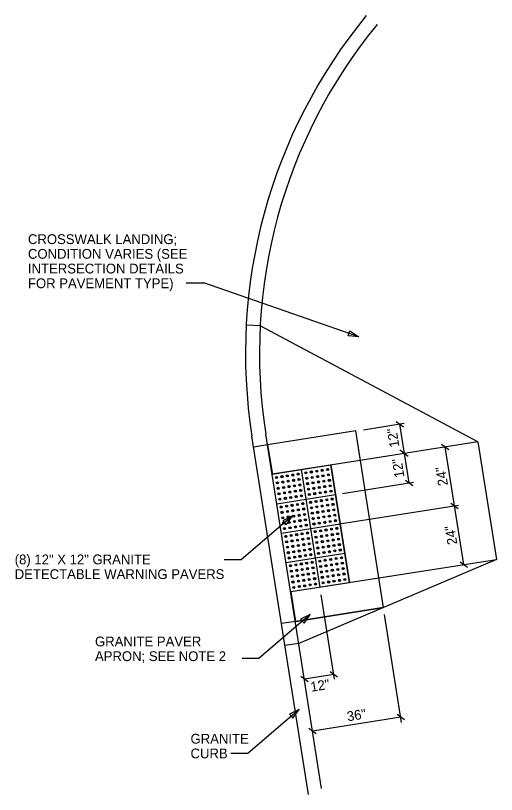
# Model space of a CAD drawing. Extents: x -848 to 1, y -1131 to -115.
# Drawn here: x -441.8 to -373.1, y -877.9 to -766.6 of the extents above; entities that cross this region are included whole.
import ezdxf

# ---------------------------------------------------------------- set-up
doc = ezdxf.new("R2010")
doc.units = 0
for name, color, linetype in [('PV_P_Curb', 7, 'Continuous'), ('PV_P_Curb_Ramp', 7, 'Continuous'), ('PV_P_Joint', 7, 'Continuous'), ('SC_Scratch3', 7, 'Continuous'), ('TX_X_5', 7, 'Continuous')]:
    doc.layers.add(name, color=color, linetype=linetype)

msp = doc.modelspace()

# ---------------------------------------------------------------- linework, layer by layer
at = {"layer": 'PV_P_Curb'}
for p, q in [((-398.03, -877.02), (-406.01, -826.38)), ((-389.2, -851.15), (-393.17, -825.94)), ((-399.92, -877.85), (-407.99, -826.69)), ((-394.06, -847.61), (-396.71, -830.8)), ((-398.26, -848.28), (-400.91, -831.46))]:
    msp.add_line(p, q, dxfattribs=at)
for radius in [76, 74]:
    msp.add_arc((-332.92, -814.85), radius, 140.6083, 188.9617, dxfattribs=at)
at = {"layer": 'PV_P_Curb_Ramp'}
for p, q in [((-406.81, -810.94), (-408.81, -810.83)), ((-375.71, -827.49), (-406.81, -810.94)), ((-393.17, -825.94), (-405.77, -827.93)), ((-375.71, -827.49), (-392.51, -830.14)), ((-375.71, -827.49), (-373.06, -844.29)), ((-405.77, -827.93), (-407.74, -828.24)), ((-392.51, -830.14), (-405.11, -832.12)), ((-404.44, -836.33), (-396.05, -835.01)), ((-403.78, -840.53), (-395.38, -839.21)), ((-403.12, -844.73), (-394.72, -843.41)), ((-373.06, -844.29), (-401.3, -856.29)), ((-389.86, -846.94), (-373.06, -844.29)), ((-389.86, -846.95), (-402.45, -848.94)), ((-389.2, -851.15), (-401.79, -853.14)), ((-401.79, -853.14), (-403.77, -853.45)), ((-401.3, -856.29), (-403.27, -856.6))]:
    msp.add_line(p, q, dxfattribs=at)
at = {"layer": 'PV_P_Joint'}
for p, q in [((-393.17, -825.94), (-405.77, -827.93)), ((-389.2, -851.15), (-393.17, -825.94)), ((-405.77, -827.93), (-405.77, -827.93)), ((-405.77, -827.93), (-405.07, -832.18)), ((-405.11, -832.12), (-396.71, -830.8)), ((-396.71, -830.8), (-394.06, -847.61)), ((-405.07, -832.18), (-405.11, -832.12)), ((-394.06, -847.61), (-402.45, -848.94))]:
    msp.add_line(p, q, dxfattribs=at)
msp.add_lwpolyline([(-402.45, -848.94), (-401.79, -853.14), (-389.2, -851.15)], dxfattribs=at)
at = {"layer": 'SC_Scratch3'}
for centre, radius in [((-401.38, -832.1), 0.15), ((-400.28, -831.93), 0.15), ((-400.28, -831.93), 0.0667), ((-400.28, -831.93), 0.0667), ((-399.5, -831.81), 0.15), ((-399.5, -831.81), 0.0667), ((-399.5, -831.81), 0.0667), ((-398.73, -831.69), 0.15), ((-398.73, -831.69), 0.0667), ((-398.73, -831.69), 0.0667), ((-397.96, -831.57), 0.15), ((-397.96, -831.57), 0.0667), ((-397.96, -831.57), 0.0667), ((-397.18, -831.45), 0.15), ((-397.18, -831.45), 0.0667), ((-397.18, -831.45), 0.0667), ((-404.48, -832.59), 0.15), ((-404.48, -832.59), 0.0667), ((-404.48, -832.59), 0.0667), ((-403.7, -832.47), 0.15), ((-403.7, -832.47), 0.0667), ((-403.7, -832.47), 0.0667), ((-403.58, -833.24), 0.15), ((-402.93, -832.35), 0.15), ((-402.93, -832.35), 0.0667), ((-402.93, -832.35), 0.0667), ((-402.81, -833.12), 0.15), ((-402.81, -833.12), 0.0667), ((-402.81, -833.12), 0.0667), ((-402.16, -832.23), 0.15), ((-402.16, -832.23), 0.0667), ((-402.16, -832.23), 0.0667), ((-402.04, -833), 0.15), ((-402.04, -833), 0.0667), ((-402.04, -833), 0.0667), ((-401.38, -832.1), 0.0667), ((-401.38, -832.1), 0.0667), ((-401.26, -832.88), 0.15), ((-401.26, -832.88), 0.0667), ((-401.26, -832.88), 0.0667), ((-400.16, -832.7), 0.15), ((-400.16, -832.7), 0.0667), ((-400.16, -832.7), 0.0667), ((-399.38, -832.58), 0.15), ((-399.38, -832.58), 0.0667), ((-399.38, -832.58), 0.0667), ((-398.61, -832.46), 0.15), ((-398.61, -832.46), 0.0667), ((-398.61, -832.46), 0.0667), ((-398.49, -833.23), 0.15), ((-397.84, -832.34), 0.15), ((-397.84, -832.34), 0.0667), ((-397.84, -832.34), 0.0667), ((-397.72, -833.11), 0.15), ((-397.72, -833.11), 0.0667), ((-397.72, -833.11), 0.0667), ((-397.06, -832.22), 0.15), ((-397.06, -832.22), 0.0667), ((-397.06, -832.22), 0.0667), ((-396.94, -832.99), 0.15), ((-396.94, -832.99), 0.0667), ((-396.94, -832.99), 0.0667), ((-404.36, -833.36), 0.15), ((-404.36, -833.36), 0.0667), ((-404.36, -833.36), 0.0667), ((-404.24, -834.13), 0.15), ((-404.24, -834.13), 0.0667), ((-404.24, -834.13), 0.0667), ((-403.58, -833.24), 0.0667), ((-403.58, -833.24), 0.0667), ((-403.46, -834.01), 0.15), ((-403.46, -834.01), 0.0667), ((-403.46, -834.01), 0.0667), ((-402.69, -833.89), 0.15), ((-402.69, -833.89), 0.0667), ((-402.69, -833.89), 0.0667), ((-401.91, -833.77), 0.15), ((-401.91, -833.77), 0.0667), ((-401.91, -833.77), 0.0667), ((-401.14, -833.65), 0.15), ((-401.14, -833.65), 0.0667), ((-401.14, -833.65), 0.0667), ((-400.04, -833.47), 0.15), ((-400.04, -833.47), 0.0667), ((-400.04, -833.47), 0.0667), ((-399.92, -834.25), 0.15), ((-399.92, -834.25), 0.0667), ((-399.92, -834.25), 0.0667), ((-399.26, -833.35), 0.15), ((-399.26, -833.35), 0.0667), ((-399.26, -833.35), 0.0667), ((-399.14, -834.13), 0.15), ((-399.14, -834.13), 0.0667), ((-399.14, -834.13), 0.0667), ((-398.49, -833.23), 0.0667), ((-398.49, -833.23), 0.0667), ((-398.37, -834.01), 0.15), ((-398.37, -834.01), 0.0667), ((-398.37, -834.01), 0.0667), ((-397.6, -833.89), 0.15), ((-397.6, -833.89), 0.0667), ((-397.6, -833.89), 0.0667), ((-396.82, -833.77), 0.15), ((-396.82, -833.77), 0.0667), ((-396.82, -833.77), 0.0667), ((-404.12, -834.91), 0.15), ((-404.12, -834.91), 0.0667), ((-404.12, -834.91), 0.0667), ((-403.34, -834.79), 0.15), ((-403.34, -834.79), 0.0667), ((-403.34, -834.79), 0.0667), ((-402.57, -834.67), 0.15), ((-402.57, -834.67), 0.0667), ((-402.57, -834.67), 0.0667), ((-402.45, -835.44), 0.15), ((-401.79, -834.55), 0.15), ((-401.79, -834.55), 0.0667), ((-401.79, -834.55), 0.0667), ((-401.67, -835.32), 0.15), ((-401.67, -835.32), 0.0667), ((-401.67, -835.32), 0.0667), ((-401.02, -834.43), 0.15), ((-401.02, -834.43), 0.0667), ((-401.02, -834.43), 0.0667), ((-400.9, -835.2), 0.15), ((-400.9, -835.2), 0.0667), ((-400.9, -835.2), 0.0667), ((-399.8, -835.02), 0.15), ((-399.8, -835.02), 0.0667), ((-399.8, -835.02), 0.0667), ((-399.02, -834.9), 0.15), ((-399.02, -834.9), 0.0667), ((-399.02, -834.9), 0.0667), ((-398.25, -834.78), 0.15), ((-398.25, -834.78), 0.0667), ((-398.25, -834.78), 0.0667), ((-397.47, -834.66), 0.15), ((-397.47, -834.66), 0.0667), ((-397.47, -834.66), 0.0667), ((-396.7, -834.54), 0.15), ((-396.7, -834.54), 0.0667), ((-396.7, -834.54), 0.0667), ((-404, -835.68), 0.15), ((-404, -835.68), 0.0667), ((-404, -835.68), 0.0667), ((-403.22, -835.56), 0.15), ((-403.22, -835.56), 0.0667), ((-403.22, -835.56), 0.0667), ((-402.45, -835.44), 0.0667), ((-402.45, -835.44), 0.0667), ((-402.26, -836.56), 0.15), ((-401.49, -836.44), 0.15), ((-401.49, -836.44), 0.0667), ((-401.49, -836.44), 0.0667), ((-400.72, -836.32), 0.15), ((-400.72, -836.32), 0.0667), ((-400.72, -836.32), 0.0667), ((-399.61, -836.14), 0.15), ((-399.61, -836.14), 0.0667), ((-399.61, -836.14), 0.0667), ((-398.84, -836.02), 0.15), ((-398.84, -836.02), 0.0667), ((-398.84, -836.02), 0.0667), ((-398.07, -835.9), 0.15), ((-398.07, -835.9), 0.0667), ((-398.07, -835.9), 0.0667), ((-397.29, -835.78), 0.15), ((-397.29, -835.78), 0.0667), ((-397.29, -835.78), 0.0667), ((-397.17, -836.55), 0.15), ((-397.17, -836.55), 0.0667), ((-397.17, -836.55), 0.0667), ((-396.52, -835.66), 0.15), ((-396.52, -835.66), 0.0667), ((-396.52, -835.66), 0.0667), ((-396.4, -836.43), 0.15), ((-396.4, -836.43), 0.0667), ((-396.4, -836.43), 0.0667), ((-403.81, -836.8), 0.15), ((-403.81, -836.8), 0.0667), ((-403.81, -836.8), 0.0667), ((-403.69, -837.57), 0.15), ((-403.69, -837.57), 0.0667), ((-403.69, -837.57), 0.0667), ((-403.04, -836.68), 0.15), ((-403.04, -836.68), 0.0667), ((-403.04, -836.68), 0.0667), ((-402.92, -837.45), 0.15), ((-402.92, -837.45), 0.0667), ((-402.92, -837.45), 0.0667), ((-402.26, -836.56), 0.0667), ((-402.26, -836.56), 0.0667), ((-402.14, -837.33), 0.15), ((-402.14, -837.33), 0.0667), ((-402.14, -837.33), 0.0667), ((-401.37, -837.21), 0.15), ((-401.37, -837.21), 0.0667), ((-401.37, -837.21), 0.0667), ((-400.6, -837.09), 0.15), ((-400.6, -837.09), 0.0667), ((-400.6, -837.09), 0.0667), ((-399.49, -836.91), 0.15), ((-399.49, -836.91), 0.0667), ((-399.49, -836.91), 0.0667), ((-399.37, -837.68), 0.15), ((-398.72, -836.79), 0.15), ((-398.72, -836.79), 0.0667), ((-398.72, -836.79), 0.0667), ((-398.6, -837.56), 0.15), ((-398.6, -837.56), 0.0667), ((-398.6, -837.56), 0.0667), ((-397.95, -836.67), 0.15), ((-397.95, -836.67), 0.0667), ((-397.95, -836.67), 0.0667), ((-397.83, -837.44), 0.15), ((-397.83, -837.44), 0.0667), ((-397.83, -837.44), 0.0667), ((-397.05, -837.32), 0.15), ((-397.05, -837.32), 0.0667), ((-397.05, -837.32), 0.0667), ((-396.28, -837.2), 0.15), ((-396.28, -837.2), 0.0667), ((-396.28, -837.2), 0.0667), ((-403.57, -838.35), 0.15), ((-403.57, -838.35), 0.0667), ((-403.57, -838.35), 0.0667), ((-402.8, -838.23), 0.15), ((-402.8, -838.23), 0.0667), ((-402.8, -838.23), 0.0667), ((-402.02, -838.11), 0.15), ((-402.02, -838.11), 0.0667), ((-402.02, -838.11), 0.0667), ((-401.25, -837.99), 0.15), ((-401.25, -837.99), 0.0667), ((-401.25, -837.99), 0.0667), ((-401.13, -838.76), 0.15), ((-401.13, -838.76), 0.0667), ((-401.13, -838.76), 0.0667), ((-400.48, -837.87), 0.15), ((-400.48, -837.87), 0.0667), ((-400.48, -837.87), 0.0667), ((-400.36, -838.64), 0.15), ((-400.36, -838.64), 0.0667), ((-400.36, -838.64), 0.0667), ((-399.37, -837.68), 0.0667), ((-399.37, -837.68), 0.0667), ((-399.25, -838.46), 0.15), ((-399.25, -838.46), 0.0667), ((-399.25, -838.46), 0.0667), ((-398.48, -838.34), 0.15), ((-398.48, -838.34), 0.0667), ((-398.48, -838.34), 0.0667), ((-397.71, -838.22), 0.15), ((-397.71, -838.22), 0.0667), ((-397.71, -838.22), 0.0667), ((-396.93, -838.1), 0.15), ((-396.93, -838.1), 0.0667), ((-396.93, -838.1), 0.0667), ((-396.16, -837.98), 0.15), ((-396.16, -837.98), 0.0667), ((-396.16, -837.98), 0.0667), ((-396.04, -838.75), 0.15), ((-396.04, -838.75), 0.0667), ((-396.04, -838.75), 0.0667), ((-403.45, -839.12), 0.15), ((-403.45, -839.12), 0.0667), ((-403.45, -839.12), 0.0667), ((-403.33, -839.89), 0.15), ((-402.68, -839), 0.15), ((-402.68, -839), 0.0667), ((-402.68, -839), 0.0667), ((-402.56, -839.77), 0.15), ((-402.56, -839.77), 0.0667), ((-402.56, -839.77), 0.0667), ((-401.9, -838.88), 0.15), ((-401.9, -838.88), 0.0667), ((-401.9, -838.88), 0.0667), ((-401.78, -839.65), 0.15), ((-401.78, -839.65), 0.0667), ((-401.78, -839.65), 0.0667), ((-401.01, -839.53), 0.15), ((-401.01, -839.53), 0.0667), ((-401.01, -839.53), 0.0667), ((-400.23, -839.41), 0.15), ((-400.23, -839.41), 0.0667), ((-400.23, -839.41), 0.0667), ((-399.13, -839.23), 0.15), ((-399.13, -839.23), 0.0667), ((-399.13, -839.23), 0.0667), ((-398.36, -839.11), 0.15), ((-398.36, -839.11), 0.0667), ((-398.36, -839.11), 0.0667), ((-397.58, -838.99), 0.15), ((-397.58, -838.99), 0.0667), ((-397.58, -838.99), 0.0667), ((-396.81, -838.87), 0.15), ((-396.81, -838.87), 0.0667), ((-396.81, -838.87), 0.0667), ((-395.86, -839.85), 0.15), ((-395.86, -839.85), 0.0667), ((-395.86, -839.85), 0.0667), ((-403.33, -839.89), 0.0667), ((-403.33, -839.89), 0.0667), ((-403.15, -841), 0.15), ((-403.15, -841), 0.0667), ((-403.15, -841), 0.0667), ((-402.38, -840.88), 0.15), ((-402.38, -840.88), 0.0667), ((-402.38, -840.88), 0.0667), ((-401.6, -840.76), 0.15), ((-401.6, -840.76), 0.0667), ((-401.6, -840.76), 0.0667), ((-400.83, -840.64), 0.15), ((-400.83, -840.64), 0.0667), ((-400.83, -840.64), 0.0667), ((-400.05, -840.52), 0.15), ((-400.05, -840.52), 0.0667), ((-400.05, -840.52), 0.0667), ((-398.95, -840.33), 0.15), ((-398.95, -840.33), 0.0667), ((-398.95, -840.33), 0.0667), ((-398.18, -840.21), 0.15), ((-398.18, -840.21), 0.0667), ((-398.18, -840.21), 0.0667), ((-398.06, -840.99), 0.15), ((-398.06, -840.99), 0.0667), ((-398.06, -840.99), 0.0667), ((-397.4, -840.09), 0.15), ((-397.4, -840.09), 0.0667), ((-397.4, -840.09), 0.0667), ((-397.28, -840.87), 0.15), ((-397.28, -840.87), 0.0667), ((-397.28, -840.87), 0.0667), ((-396.63, -839.97), 0.15), ((-396.63, -839.97), 0.0667), ((-396.63, -839.97), 0.0667), ((-396.51, -840.75), 0.15), ((-396.51, -840.75), 0.0667), ((-396.51, -840.75), 0.0667), ((-395.74, -840.63), 0.15), ((-395.74, -840.63), 0.0667), ((-395.74, -840.63), 0.0667), ((-403.03, -841.77), 0.15), ((-403.03, -841.77), 0.0667), ((-403.03, -841.77), 0.0667), ((-402.26, -841.65), 0.15), ((-402.26, -841.65), 0.0667), ((-402.26, -841.65), 0.0667), ((-401.48, -841.53), 0.15), ((-401.48, -841.53), 0.0667), ((-401.48, -841.53), 0.0667), ((-400.71, -841.41), 0.15), ((-400.71, -841.41), 0.0667), ((-400.71, -841.41), 0.0667), ((-400.59, -842.18), 0.15), ((-399.93, -841.29), 0.15), ((-399.93, -841.29), 0.0667), ((-399.93, -841.29), 0.0667), ((-399.81, -842.06), 0.15), ((-399.81, -842.06), 0.0667), ((-399.81, -842.06), 0.0667), ((-398.83, -841.11), 0.15), ((-398.83, -841.11), 0.0667), ((-398.83, -841.11), 0.0667), ((-398.71, -841.88), 0.15), ((-398.71, -841.88), 0.0667), ((-398.71, -841.88), 0.0667), ((-397.94, -841.76), 0.15), ((-397.94, -841.76), 0.0667), ((-397.94, -841.76), 0.0667), ((-397.16, -841.64), 0.15), ((-397.16, -841.64), 0.0667), ((-397.16, -841.64), 0.0667), ((-396.39, -841.52), 0.15), ((-396.39, -841.52), 0.0667), ((-396.39, -841.52), 0.0667), ((-395.62, -841.4), 0.15), ((-395.62, -841.4), 0.0667), ((-395.62, -841.4), 0.0667), ((-395.5, -842.18), 0.15), ((-402.91, -842.54), 0.15), ((-402.91, -842.54), 0.0667), ((-402.91, -842.54), 0.0667), ((-402.14, -842.42), 0.15), ((-402.14, -842.42), 0.0667), ((-402.14, -842.42), 0.0667), ((-402.02, -843.2), 0.15), ((-402.02, -843.2), 0.0667), ((-402.02, -843.2), 0.0667), ((-401.36, -842.3), 0.15), ((-401.36, -842.3), 0.0667), ((-401.36, -842.3), 0.0667), ((-401.24, -843.08), 0.15), ((-401.24, -843.08), 0.0667), ((-401.24, -843.08), 0.0667), ((-400.59, -842.18), 0.0667), ((-400.59, -842.18), 0.0667), ((-400.47, -842.96), 0.15), ((-400.47, -842.96), 0.0667), ((-400.47, -842.96), 0.0667), ((-399.69, -842.84), 0.15), ((-399.69, -842.84), 0.0667), ((-399.69, -842.84), 0.0667), ((-398.59, -842.66), 0.15), ((-398.59, -842.66), 0.0667), ((-398.59, -842.66), 0.0667), ((-397.82, -842.54), 0.15), ((-397.82, -842.54), 0.0667), ((-397.82, -842.54), 0.0667), ((-397.04, -842.42), 0.15), ((-397.04, -842.42), 0.0667), ((-397.04, -842.42), 0.0667), ((-396.92, -843.19), 0.15), ((-396.92, -843.19), 0.0667), ((-396.92, -843.19), 0.0667), ((-396.27, -842.3), 0.15), ((-396.27, -842.3), 0.0667), ((-396.27, -842.3), 0.0667), ((-396.15, -843.07), 0.15), ((-396.15, -843.07), 0.0667), ((-396.15, -843.07), 0.0667), ((-395.5, -842.18), 0.0667), ((-395.5, -842.18), 0.0667), ((-395.37, -842.95), 0.15), ((-395.37, -842.95), 0.0667), ((-395.37, -842.95), 0.0667), ((-402.79, -843.32), 0.15), ((-402.79, -843.32), 0.0667), ((-402.79, -843.32), 0.0667), ((-402.67, -844.09), 0.15), ((-402.67, -844.09), 0.0667), ((-402.67, -844.09), 0.0667), ((-401.89, -843.97), 0.15), ((-401.89, -843.97), 0.0667), ((-401.89, -843.97), 0.0667), ((-401.12, -843.85), 0.15), ((-401.12, -843.85), 0.0667), ((-401.12, -843.85), 0.0667), ((-400.35, -843.73), 0.15), ((-400.35, -843.73), 0.0667), ((-400.35, -843.73), 0.0667), ((-399.57, -843.61), 0.15), ((-399.57, -843.61), 0.0667), ((-399.57, -843.61), 0.0667), ((-398.47, -843.43), 0.15), ((-398.47, -843.43), 0.0667), ((-398.47, -843.43), 0.0667), ((-397.7, -843.31), 0.15), ((-397.7, -843.31), 0.0667), ((-397.7, -843.31), 0.0667), ((-397.52, -844.41), 0.15), ((-396.74, -844.29), 0.15), ((-396.74, -844.29), 0.0667), ((-396.74, -844.29), 0.0667), ((-395.97, -844.17), 0.15), ((-395.97, -844.17), 0.0667), ((-395.97, -844.17), 0.0667), ((-395.19, -844.05), 0.15), ((-395.19, -844.05), 0.0667), ((-395.19, -844.05), 0.0667), ((-402.49, -845.19), 0.15), ((-402.49, -845.19), 0.0667), ((-402.49, -845.19), 0.0667), ((-401.71, -845.07), 0.15), ((-401.71, -845.07), 0.0667), ((-401.71, -845.07), 0.0667), ((-400.94, -844.95), 0.15), ((-400.94, -844.95), 0.0667), ((-400.94, -844.95), 0.0667), ((-400.17, -844.83), 0.15), ((-400.17, -844.83), 0.0667), ((-400.17, -844.83), 0.0667), ((-399.39, -844.71), 0.15), ((-399.39, -844.71), 0.0667), ((-399.39, -844.71), 0.0667), ((-399.27, -845.49), 0.15), ((-398.29, -844.53), 0.15), ((-398.29, -844.53), 0.0667), ((-398.29, -844.53), 0.0667), ((-398.17, -845.31), 0.15), ((-398.17, -845.31), 0.0667), ((-398.17, -845.31), 0.0667), ((-397.52, -844.41), 0.0667), ((-397.52, -844.41), 0.0667), ((-397.4, -845.19), 0.15), ((-397.4, -845.19), 0.0667), ((-397.4, -845.19), 0.0667), ((-396.62, -845.07), 0.15), ((-396.62, -845.07), 0.0667), ((-396.62, -845.07), 0.0667), ((-395.85, -844.95), 0.15), ((-395.85, -844.95), 0.0667), ((-395.85, -844.95), 0.0667), ((-395.07, -844.83), 0.15), ((-395.07, -844.83), 0.0667), ((-395.07, -844.83), 0.0667), ((-402.37, -845.97), 0.15), ((-402.37, -845.97), 0.0667), ((-402.37, -845.97), 0.0667), ((-401.59, -845.85), 0.15), ((-401.59, -845.85), 0.0667), ((-401.59, -845.85), 0.0667), ((-401.47, -846.62), 0.15), ((-400.82, -845.73), 0.15), ((-400.82, -845.73), 0.0667), ((-400.82, -845.73), 0.0667), ((-400.7, -846.5), 0.15), ((-400.7, -846.5), 0.0667), ((-400.7, -846.5), 0.0667), ((-400.05, -845.61), 0.15), ((-400.05, -845.61), 0.0667), ((-400.05, -845.61), 0.0667), ((-399.93, -846.38), 0.15), ((-399.93, -846.38), 0.0667), ((-399.93, -846.38), 0.0667), ((-399.27, -845.49), 0.0667), ((-399.27, -845.49), 0.0667), ((-399.15, -846.26), 0.15), ((-399.15, -846.26), 0.0667), ((-399.15, -846.26), 0.0667), ((-398.05, -846.08), 0.15), ((-398.05, -846.08), 0.0667), ((-398.05, -846.08), 0.0667), ((-397.28, -845.96), 0.15), ((-397.28, -845.96), 0.0667), ((-397.28, -845.96), 0.0667), ((-396.5, -845.84), 0.15), ((-396.5, -845.84), 0.0667), ((-396.5, -845.84), 0.0667), ((-396.38, -846.61), 0.15), ((-395.73, -845.72), 0.15), ((-395.73, -845.72), 0.0667), ((-395.73, -845.72), 0.0667), ((-395.61, -846.49), 0.15), ((-395.61, -846.49), 0.0667), ((-395.61, -846.49), 0.0667), ((-394.95, -845.6), 0.15), ((-394.95, -845.6), 0.0667), ((-394.95, -845.6), 0.0667), ((-394.83, -846.37), 0.15), ((-394.83, -846.37), 0.0667), ((-394.83, -846.37), 0.0667), ((-402.25, -846.74), 0.15), ((-402.25, -846.74), 0.0667), ((-402.25, -846.74), 0.0667), ((-402.13, -847.52), 0.15), ((-402.13, -847.52), 0.0667), ((-402.13, -847.52), 0.0667), ((-401.47, -846.62), 0.0667), ((-401.47, -846.62), 0.0667), ((-401.35, -847.4), 0.15), ((-401.35, -847.4), 0.0667), ((-401.35, -847.4), 0.0667), ((-400.58, -847.28), 0.15), ((-400.58, -847.28), 0.0667), ((-400.58, -847.28), 0.0667), ((-399.81, -847.16), 0.15), ((-399.81, -847.16), 0.0667), ((-399.81, -847.16), 0.0667), ((-399.03, -847.04), 0.15), ((-399.03, -847.04), 0.0667), ((-399.03, -847.04), 0.0667), ((-397.93, -846.85), 0.15), ((-397.93, -846.85), 0.0667), ((-397.93, -846.85), 0.0667), ((-397.81, -847.63), 0.15), ((-397.81, -847.63), 0.0667), ((-397.81, -847.63), 0.0667), ((-397.16, -846.73), 0.15), ((-397.16, -846.73), 0.0667), ((-397.16, -846.73), 0.0667), ((-397.03, -847.51), 0.15), ((-397.03, -847.51), 0.0667), ((-397.03, -847.51), 0.0667), ((-396.38, -846.61), 0.0667), ((-396.38, -846.61), 0.0667), ((-396.26, -847.39), 0.15), ((-396.26, -847.39), 0.0667), ((-396.26, -847.39), 0.0667), ((-395.49, -847.27), 0.15), ((-395.49, -847.27), 0.0667), ((-395.49, -847.27), 0.0667), ((-394.71, -847.15), 0.15), ((-394.71, -847.15), 0.0667), ((-394.71, -847.15), 0.0667), ((-402.01, -848.29), 0.15), ((-402.01, -848.29), 0.0667), ((-402.01, -848.29), 0.0667), ((-401.23, -848.17), 0.15), ((-401.23, -848.17), 0.0667), ((-401.23, -848.17), 0.0667), ((-400.46, -848.05), 0.15), ((-400.46, -848.05), 0.0667), ((-400.46, -848.05), 0.0667), ((-399.68, -847.93), 0.15), ((-399.68, -847.93), 0.0667), ((-399.68, -847.93), 0.0667), ((-398.91, -847.81), 0.15), ((-398.91, -847.81), 0.0667), ((-398.91, -847.81), 0.0667)]:
    msp.add_circle(centre, radius, dxfattribs=at)
at = {"layer": 'TX_X_5'}
for p, q in [((-417.38, -804.79), (-414.88, -804.79)), ((-392.7, -812.5), (-414.88, -804.79)), ((-392.05, -825.77), (-386.22, -824.85)), ((-387.38, -824.57), (-386.33, -825.33)), ((-385.53, -833.35), (-386.86, -824.95)), ((-386.88, -828.64), (-385.67, -829.52)), ((-380.91, -827.84), (-379.86, -828.61)), ((-377.73, -845.03), (-380.39, -828.23)), ((-386.05, -832.97), (-385, -833.73)), ((-395.07, -834.86), (-384.89, -833.25)), ((-379.58, -836.25), (-378.53, -837.01)), ((-395.49, -839.23), (-378.47, -836.53)), ((-402.21, -838.07), (-409.49, -844.31)), ((-411.96, -844.31), (-409.49, -844.31)), ((-378.25, -844.65), (-377.2, -845.41)), ((-396.18, -861.39), (-398.09, -849.33)), ((-399.66, -852.14), (-406.94, -858.38)), ((-386.6, -867.57), (-389.04, -852.17)), ((-409.41, -858.38), (-406.94, -858.38)), ((-400.5, -861.34), (-396.29, -860.68)), ((-396.82, -860.3), (-395.77, -861.06)), ((-401.02, -860.96), (-399.97, -861.73)), ((-401.24, -865.72), (-408.52, -871.96)), ((-387.25, -866.41), (-386.2, -867.17)), ((-399.32, -868.78), (-386.72, -866.79)), ((-399.85, -868.4), (-398.8, -869.16)), ((-410.99, -871.96), (-408.52, -871.96))]:
    msp.add_line(p, q, dxfattribs=at)
for points in [[(-393.99, -811.66), (-392.7, -812.5), (-394.24, -812.36)], [(-403.1, -839.33), (-402.21, -838.07), (-403.59, -838.76)], [(-400.55, -853.4), (-399.66, -852.14), (-401.04, -852.83)], [(-402.14, -866.98), (-401.24, -865.72), (-402.63, -866.41)]]:
    msp.add_lwpolyline(points, close=True, dxfattribs=at)

# ---------------------------------------------------------------- texts
for s, p in [('CROSSWALK LANDING;', (-440, -799.25)), ('CONDITION VARIES (SEE', (-440, -801.35)), ('INTERSECTION DETAILS', (-440, -803.45)), ('FOR PAVEMENT TYPE) ', (-440, -805.55)), ('(8) 12" X 12" GRANITE', (-441.89, -844.99)), ('DETECTABLE WARNING PAVERS', (-441.89, -847.09)), ('GRANITE PAVER', (-430.42, -856.71)), ('APRON; SEE NOTE 2', (-430.42, -858.81)), ('GRANITE', (-416.77, -870.6)), ('CURB', (-416.77, -872.7))]:
    msp.add_text(s, height=1.4, dxfattribs=at).set_placement(p)
for s, rotation, p in [('12"', 99.2491, (-386.91, -828.17)), ('12"', 99.2491, (-386.19, -832.5)), ('24"', 99.2491, (-379.97, -833.67)), ('24"', 99.2491, (-378.64, -842.08)), ('12"', 9.2491, (-399.51, -863.2)), ('36"', 9.2491, (-394.3, -867.43))]:
    msp.add_text(s, height=1.4, rotation=rotation, dxfattribs=at).set_placement(p)

doc.saveas('drawing.dxf')
